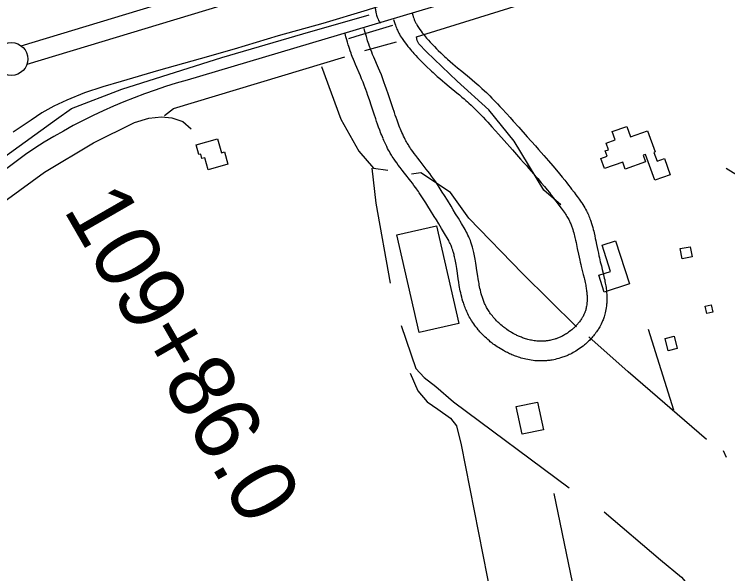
# Model space of a CAD drawing. Extents: x 3146026 to 3183936, y 897894 to 923344.
# Drawn here: x 3163729 to 3164815, y 911183 to 912036 of the extents above; entities that cross this region are included whole.
import ezdxf

# ---------------------------------------------------------------- set-up
doc = ezdxf.new("R2010")
doc.units = 0
for name, color, linetype in [('V-BLDG-OTLN', 7, 'Continuous'), ('V-LEVE-TOET', 7, 'Continuous'), ('V-ROAD-CNTR', 7, 'Continuous'), ('V-SURV-IDEN', 7, 'Continuous'), ('V-SURV-LINE', 7, 'Continuous'), ('V-TOPO-SHOR', 7, 'Continuous')]:
    doc.layers.add(name, color=color, linetype=linetype)

msp = doc.modelspace()

# ---------------------------------------------------------------- linework, layer by layer
at = {"layer": 'V-BLDG-OTLN'}
for points in [[(3164727.9, 911791.2), (3164704.4, 911782.8), (3164690.3, 911822.1), (3164686.8, 911820.8), (3164690.3, 911810.9), (3164659.4, 911799.8), (3164655.6, 911810.5), (3164627.9, 911800.5), (3164622.4, 911815.9), (3164631.8, 911819.3), (3164628.9, 911827.4), (3164634, 911829.3), (3164630.3, 911839.4), (3164644.1, 911844.4), (3164639.6, 911856.8), (3164661.8, 911864.8), (3164667.6, 911848.7), (3164693.4, 911857.9), (3164704.9, 911825.8), (3164703.1, 911825.1), (3164707.9, 911811.7), (3164719.1, 911815.7)], [(3164054.6, 911807.3), (3164024.3, 911798.7), (3164019.1, 911817), (3164014.8, 911815.8), (3164013, 911822.4), (3164010.3, 911821.7), (3164006.1, 911836.6), (3164038.5, 911845.8), (3164044.5, 911824.7), (3164049.3, 911826.1)], [(3164311.8, 911699.6), (3164371.9, 911713.3), (3164406, 911564.6), (3164345.9, 911550.8)], [(3164665.9, 911624.9), (3164627.4, 911612.4), (3164619.1, 911638), (3164637, 911643.8), (3164624.1, 911683.7), (3164644.6, 911690.4)], [(3164761.4, 911666), (3164746.2, 911663.2), (3164743.3, 911678.7), (3164758.5, 911681.5)], [(3164792.9, 911581.9), (3164783.8, 911579.9), (3164781.3, 911590.9), (3164790.4, 911593)], [(3164733.7, 911545.1), (3164738.4, 911526.5), (3164725, 911523.1), (3164720.3, 911541.7)], [(3164493.4, 911438), (3164526.1, 911444.8), (3164535, 911402.6), (3164502.3, 911395.7)]]:
    msp.add_lwpolyline(points, close=True, dxfattribs=at)
at = {"layer": 'V-LEVE-TOET'}
msp.add_lwpolyline([(3164860.5, 912225.7), (3164786.2, 912200.7), (3164711.4, 912177.3), (3164636.1, 912155.4), (3164583.4, 912141), (3164444.8, 912098.4), (3164414.2, 912089), (3164373.8, 912077.4), (3164333.9, 912064.4), (3164309.7, 912055.7), (3164266.4, 912041.7), (3164199, 912021.6), (3164131.2, 912002.8), (3164063.8, 911982.2), (3164012.4, 911967.6), (3163949, 911950.1), (3163891.7, 911932.9), (3163863.8, 911925.1), (3163836.3, 911915.7), (3163809.4, 911904.9), (3163789.6, 911895.6), (3163771.3, 911885.2), (3163754.8, 911874.1), (3163727.7, 911855.9)], dxfattribs=at)
at = {"layer": 'V-ROAD-CNTR'}
for p, q in [((3164250, 912002.2), (3164305.4, 912018.9)), ((3164238.6, 911998.7), (3164250, 912002.2))]:
    msp.add_line(p, q, dxfattribs=at)
for points in [[(3165388.2, 912351.5), (3163992.3, 911935.1)], [(3164278.7, 912047.4), (3164278.7, 912046), (3164278.9, 912044.2), (3164279, 912042.7), (3164279.2, 912041.2), (3164279.5, 912039.8), (3164279.7, 912038.5), (3164280.3, 912036.3), (3164280.8, 912034.4), (3164281.4, 912032.7), (3164281.9, 912031.2), (3164282.4, 912029.9), (3164283.3, 912027.9), (3164284, 912026.3), (3164285.1, 912024.1), (3164286.2, 912022.2)], [(3164334.8, 912037), (3164335.8, 912034.1), (3164336.7, 912031.6), (3164337.5, 912029.6), (3164338.1, 912027.8), (3164338.8, 912026.3), (3164339.3, 912025.1), (3164339.8, 912024), (3164340.7, 912022.1), (3164341.4, 912020.8), (3164341.9, 912019.8), (3164342.8, 912018.4), (3164343.7, 912016.9), (3164344.6, 912015.4), (3164345.6, 912014), (3164346.5, 912012.6), (3164348.5, 912009.9), (3164350.3, 912007.5), (3164352.1, 912005.2), (3164353.8, 912003.1), (3164355.4, 912001.1), (3164356.9, 911999.3), (3164358.4, 911997.6), (3164359.8, 911996.1), (3164362.5, 911993.1), (3164364.9, 911990.5), (3164367, 911988.3), (3164368.9, 911986.4), (3164372.3, 911983), (3164374.8, 911980.5), (3164378.8, 911976.7), (3164382.8, 911972.9), (3164384.9, 911970.9), (3164387, 911969), (3164389, 911967.1), (3164393.1, 911963.5), (3164396.9, 911960.2), (3164400.5, 911957.1), (3164404, 911954.2), (3164410.5, 911948.8), (3164422.1, 911939.2), (3164426.5, 911935.5), (3164430.3, 911932.2), (3164433.6, 911929.4), (3164436.5, 911926.8), (3164439.1, 911924.6), (3164441.3, 911922.6), (3164445.2, 911919), (3164448.1, 911916.3), (3164450.2, 911914.2), (3164453.4, 911911.1), (3164456.5, 911907.9), (3164460.9, 911903.4), (3164464.9, 911899.2), (3164468.6, 911895.2), (3164472.1, 911891.5), (3164478.5, 911884.5), (3164484.2, 911878.3), (3164489, 911872.9), (3164497.5, 911863.4), (3164510.1, 911849.1), (3164522.7, 911834.9), (3164527.2, 911829.8), (3164531.4, 911825), (3164535.4, 911820.5), (3164542.7, 911812.1), (3164549.1, 911804.6), (3164554.6, 911798.1), (3164559.4, 911792.3), (3164563.6, 911787.2), (3164567.3, 911782.6), (3164570.5, 911778.6), (3164573.2, 911775.1), (3164575.7, 911772), (3164577.8, 911769.2), (3164581.5, 911764.4), (3164584.2, 911760.7), (3164586.3, 911757.9), (3164589.4, 911753.7), (3164592.4, 911749.3), (3164593.3, 911748.1), (3164594.9, 911745.6), (3164596.4, 911743.2), (3164597.8, 911740.8), (3164599.1, 911738.5), (3164600.3, 911736.2), (3164601.3, 911734.1)], [(3164306.4, 912027.4), (3164307.5, 912024.3), (3164308.5, 912021.4), (3164309.4, 912018.9), (3164310.3, 912016.7), (3164311.1, 912014.7), (3164311.9, 912012.9), (3164312.6, 912011.4), (3164313.8, 912008.7), (3164314.9, 912006.7), (3164315.7, 912005.1), (3164317, 912002.9), (3164318.4, 912000.7), (3164319.6, 911998.8), (3164320.8, 911997.1), (3164322, 911995.4), (3164324.2, 911992.2), (3164326.4, 911989.3), (3164328.5, 911986.6), (3164330.5, 911984.2), (3164332.4, 911981.9), (3164334.1, 911979.8), (3164335.8, 911977.8), (3164337.4, 911976), (3164340.4, 911972.7), (3164343.1, 911969.9), (3164345.5, 911967.4), (3164347.5, 911965.3), (3164351.2, 911961.7), (3164353.9, 911959), (3164358, 911955), (3164362.2, 911951.1), (3164364.5, 911948.9), (3164366.8, 911946.8), (3164369, 911944.8), (3164373.3, 911941), (3164377.3, 911937.5), (3164381.1, 911934.2), (3164384.7, 911931.2), (3164391.3, 911925.7), (3164402.9, 911916.1), (3164407.1, 911912.6), (3164410.8, 911909.4), (3164414, 911906.7), (3164416.7, 911904.3), (3164419.1, 911902.2), (3164421.2, 911900.3), (3164424.8, 911897), (3164427.4, 911894.6), (3164429.3, 911892.7), (3164432.2, 911889.9), (3164435, 911887), (3164439.2, 911882.7), (3164443.1, 911878.6), (3164446.7, 911874.7), (3164450.1, 911871.1), (3164456.4, 911864.2), (3164461.9, 911858.2), (3164466.7, 911852.9), (3164475.1, 911843.5), (3164487.6, 911829.3), (3164500.2, 911815), (3164504.7, 911809.9), (3164508.9, 911805.2), (3164512.8, 911800.8), (3164520, 911792.5), (3164526.2, 911785.2), (3164531.6, 911778.8), (3164536.3, 911773.2), (3164540.4, 911768.2), (3164543.9, 911763.9), (3164546.9, 911760), (3164549.6, 911756.6), (3164551.9, 911753.6), (3164554, 911751), (3164557.5, 911746.4), (3164560.1, 911742.8), (3164562.1, 911740.2), (3164565, 911736.2), (3164567.9, 911732.1), (3164568.5, 911731.2), (3164569.7, 911729.4), (3164570.7, 911727.7), (3164571.7, 911726), (3164572.7, 911724.3), (3164573.5, 911722.7), (3164574.4, 911720.9)], [(3164290.8, 911846.1), (3164289.7, 911848.8), (3164288.6, 911851.5), (3164287.5, 911854.1), (3164285.6, 911859.1), (3164283.8, 911863.8), (3164282.2, 911868.2), (3164280.8, 911872.3), (3164279.5, 911876.2), (3164277, 911883.4), (3164272.9, 911895.8), (3164269.9, 911905.1), (3164267.6, 911912), (3164265.8, 911917), (3164264.4, 911920.8), (3164263.4, 911923.6), (3164261.8, 911927.8), (3164260.2, 911931.9), (3164258, 911937.3), (3164256.1, 911942), (3164248.9, 911958.8), (3164247.1, 911963.1), (3164245.8, 911966.4), (3164243.8, 911971.3), (3164242.8, 911973.8), (3164241.9, 911976.4), (3164240.6, 911980.1), (3164239.4, 911983.4), (3164238.5, 911986.3), (3164237.7, 911988.8), (3164236.4, 911993.1), (3164235.5, 911996.4), (3164234.2, 912001.3), (3164232.9, 912006.1)], [(3164318.4, 911857.8), (3164317.4, 911860.3), (3164316.4, 911862.8), (3164315.4, 911865.1), (3164313.6, 911869.7), (3164312, 911874.1), (3164310.5, 911878.2), (3164309.1, 911882.1), (3164307.9, 911885.8), (3164305.5, 911892.8), (3164301.4, 911905.2), (3164298.3, 911914.6), (3164295.9, 911921.7), (3164294.1, 911927), (3164292.6, 911931), (3164291.5, 911934.1), (3164289.8, 911938.6), (3164288.1, 911943.1), (3164285.8, 911948.8), (3164283.7, 911953.7), (3164276.5, 911970.4), (3164274.8, 911974.5), (3164273.6, 911977.6), (3164271.8, 911982.2), (3164270.9, 911984.4), (3164270.1, 911986.7), (3164268.9, 911990), (3164267.9, 911992.8), (3164267.1, 911995.3), (3164266.4, 911997.5), (3164265.3, 912001.5), (3164264.4, 912004.5), (3164263.2, 912009.1), (3164261.9, 912013.7)], [(3164451.3, 911584.2), (3164450.2, 911585.9), (3164449.3, 911587.5), (3164448.4, 911589.1), (3164447.6, 911590.6), (3164446.8, 911592.2), (3164446.1, 911593.7), (3164445.4, 911595.2), (3164444.8, 911596.7), (3164444.1, 911598.2), (3164443.6, 911599.7), (3164443, 911601.2), (3164442.5, 911602.6), (3164442, 911604), (3164441.5, 911605.4), (3164441.1, 911606.8), (3164440.3, 911609.6), (3164439.5, 911612.4), (3164438.9, 911615.1), (3164438.3, 911617.7), (3164437.7, 911620.2), (3164437.2, 911622.8), (3164436.8, 911625.2), (3164436.3, 911627.6), (3164435.6, 911632.3), (3164434.9, 911636.8), (3164433.6, 911645.3), (3164432.5, 911652.8), (3164432, 911656.2), (3164431.5, 911659.4), (3164431, 911662.4), (3164430.5, 911665.2), (3164429.9, 911667.8), (3164429.4, 911670.3), (3164428.9, 911672.6), (3164428.4, 911674.8), (3164427.9, 911676.9), (3164427.4, 911678.8), (3164426.9, 911680.6), (3164426.4, 911682.4), (3164425.4, 911685.5), (3164424.5, 911688.3), (3164423.6, 911690.8), (3164422.8, 911692.9), (3164422, 911694.8), (3164421.3, 911696.5), (3164420, 911699.3), (3164419, 911701.4), (3164418.2, 911703), (3164416.9, 911705.4), (3164415.6, 911707.7), (3164410.2, 911716.8), (3164405.4, 911724.8), (3164401.2, 911731.7), (3164397.6, 911737.8), (3164394.3, 911743.1), (3164388.6, 911752.4), (3164384.2, 911759.4), (3164380.9, 911764.6), (3164375.9, 911772.4), (3164370.9, 911780.1), (3164369.3, 911782.5), (3164367.7, 911784.7), (3164366.2, 911786.9), (3164364.7, 911788.9), (3164361.9, 911792.8), (3164359.1, 911796.5), (3164356.5, 911799.8), (3164347, 911811.9), (3164343.5, 911816.4), (3164340.6, 911820.2), (3164338, 911823.6), (3164335.9, 911826.5), (3164334.1, 911829.1), (3164332.6, 911831.3), (3164331.3, 911833.3), (3164330.1, 911835.1), (3164329.2, 911836.5), (3164327.6, 911839.2), (3164326.4, 911841.3), (3164325.6, 911842.7), (3164324.4, 911845), (3164323.2, 911847.4), (3164321.9, 911850.1), (3164320.7, 911852.7), (3164319.5, 911855.3), (3164318.4, 911857.9)], [(3164425.7, 911568.5), (3164424.4, 911570.6), (3164423.2, 911572.7), (3164422, 911574.8), (3164420.9, 911576.9), (3164419.9, 911579), (3164418.9, 911581.1), (3164418, 911583.1), (3164417.1, 911585), (3164416.3, 911587), (3164415.6, 911588.9), (3164414.9, 911590.8), (3164414.2, 911592.7), (3164413.6, 911594.5), (3164413, 911596.3), (3164412.4, 911598.1), (3164411.4, 911601.5), (3164410.5, 911604.8), (3164409.7, 911608.1), (3164409, 911611.2), (3164408.3, 911614.2), (3164407.8, 911617), (3164407.2, 911619.8), (3164406.8, 911622.5), (3164405.9, 911627.6), (3164405.2, 911632.3), (3164403.9, 911641), (3164402.9, 911648.4), (3164402.4, 911651.5), (3164401.9, 911654.4), (3164401.4, 911657.1), (3164401, 911659.6), (3164400.5, 911661.9), (3164400.1, 911664), (3164399.7, 911666), (3164399.2, 911667.8), (3164398.8, 911669.5), (3164398.4, 911671), (3164398, 911672.5), (3164397.6, 911673.8), (3164396.8, 911676.3), (3164396.1, 911678.5), (3164395.5, 911680.3), (3164394.9, 911681.9), (3164394.3, 911683.3), (3164393.8, 911684.4), (3164392.9, 911686.5), (3164392.1, 911688.1), (3164391.6, 911689.1), (3164390.7, 911690.8), (3164389.7, 911692.6), (3164384.4, 911701.5), (3164379.7, 911709.4), (3164375.6, 911716.2), (3164371.9, 911722.2), (3164368.7, 911727.4), (3164363.1, 911736.6), (3164358.8, 911743.4), (3164355.6, 911748.5), (3164350.7, 911756.1), (3164345.8, 911763.6), (3164344.5, 911765.6), (3164343.1, 911767.6), (3164341.8, 911769.5), (3164340.5, 911771.3), (3164337.8, 911774.9), (3164335.3, 911778.2), (3164332.9, 911781.3), (3164323.4, 911793.4), (3164319.8, 911798), (3164316.6, 911802.1), (3164313.9, 911805.8), (3164311.5, 911809.1), (3164309.4, 911812), (3164307.7, 911814.6), (3164306.1, 911816.9), (3164304.8, 911819), (3164303.7, 911820.8), (3164301.7, 911824), (3164300.3, 911826.5), (3164299.2, 911828.4), (3164297.7, 911831.2), (3164296.3, 911834.1), (3164294.8, 911837.3), (3164293.4, 911840.3), (3164292.1, 911843.2), (3164290.9, 911846)], [(3163746.4, 911822.1), (3163589.8, 911705), (3162975.7, 911197.8)], [(3164601.4, 911733.8), (3164602.4, 911731.9), (3164603.3, 911729.8), (3164604.1, 911727.8), (3164604.9, 911725.8), (3164605.6, 911723.9), (3164606.3, 911722.1), (3164607, 911720.2), (3164608.1, 911716.8), (3164609.1, 911713.6), (3164610, 911710.6), (3164610.7, 911707.7), (3164611.4, 911705.1), (3164612, 911702.6), (3164613.1, 911698.1), (3164613.9, 911694.1), (3164614.7, 911690.6), (3164615.9, 911684.7), (3164617.6, 911675.9), (3164618.5, 911671.7), (3164619.4, 911667.6), (3164620.1, 911664.5), (3164620.8, 911661.4), (3164621.5, 911658.5), (3164623.1, 911652.5), (3164624.5, 911646.7), (3164625.9, 911641.2), (3164626.5, 911638.6), (3164627.1, 911636), (3164627.6, 911633.5), (3164628.2, 911631), (3164628.6, 911628.6), (3164629.1, 911626.2), (3164629.5, 911623.9), (3164629.8, 911621.7), (3164630.2, 911619.5), (3164630.4, 911617.4), (3164630.7, 911615.3), (3164630.9, 911613.2), (3164631.1, 911611.3), (3164631.2, 911609.3), (3164631.3, 911607.4), (3164631.4, 911605.6), (3164631.4, 911603.8), (3164631.4, 911602.1), (3164631.4, 911600.4), (3164631.4, 911598.8), (3164631.3, 911597.2), (3164631.2, 911595.6), (3164631.1, 911594), (3164630.8, 911591.2), (3164630.5, 911588.4), (3164630.1, 911585.8), (3164629.6, 911583.3), (3164629.1, 911581), (3164628.5, 911578.9), (3164628, 911576.8), (3164627.4, 911574.9), (3164626.8, 911573.2), (3164626.2, 911571.5), (3164625.6, 911569.9), (3164625, 911568.5), (3164624.5, 911567.1), (3164623.9, 911565.8), (3164622.7, 911563.5), (3164621.7, 911561.4), (3164620.7, 911559.6), (3164619.8, 911558), (3164618.9, 911556.6), (3164618.2, 911555.4), (3164616.8, 911553.3), (3164615.7, 911551.8), (3164614.9, 911550.6), (3164613.6, 911548.9), (3164612.2, 911547.2), (3164611, 911545.6), (3164609.7, 911544.2), (3164608.5, 911542.8), (3164607.2, 911541.4), (3164606, 911540.1), (3164604.8, 911538.8), (3164603.5, 911537.6), (3164602.3, 911536.4), (3164601.1, 911535.3), (3164599.9, 911534.2), (3164598.7, 911533.1), (3164597.6, 911532.2)], [(3164574.2, 911721.2), (3164575, 911719.5), (3164575.7, 911717.9), (3164576.4, 911716.4), (3164577, 911714.8), (3164577.6, 911713.4), (3164578.1, 911711.9), (3164578.6, 911710.5), (3164579.5, 911707.7), (3164580.3, 911705), (3164581.1, 911702.5), (3164581.7, 911700.1), (3164582.3, 911697.8), (3164582.8, 911695.6), (3164583.8, 911691.5), (3164584.6, 911687.8), (3164585.3, 911684.6), (3164586.4, 911678.8), (3164588.2, 911670), (3164589.1, 911665.5), (3164590.1, 911661.1), (3164590.9, 911657.7), (3164591.6, 911654.4), (3164592.4, 911651.2), (3164594, 911645.1), (3164595.4, 911639.4), (3164596.7, 911634.2), (3164597.3, 911631.8), (3164597.8, 911629.4), (3164598.3, 911627.2), (3164598.8, 911625), (3164599.2, 911622.9), (3164599.6, 911620.9), (3164599.9, 911619), (3164600.2, 911617.1), (3164600.5, 911615.4), (3164600.7, 911613.6), (3164600.9, 911612), (3164601, 911610.4), (3164601.2, 911608.9), (3164601.3, 911607.4), (3164601.3, 911606), (3164601.4, 911604.7), (3164601.4, 911603.4), (3164601.4, 911602.1), (3164601.4, 911600.9), (3164601.4, 911599.7), (3164601.4, 911598.6), (3164601.3, 911597.6), (3164601.2, 911596.6), (3164601, 911594.5), (3164600.8, 911592.7), (3164600.5, 911591), (3164600.2, 911589.4), (3164599.9, 911587.9), (3164599.5, 911586.5), (3164599.2, 911585.2), (3164598.8, 911584), (3164598.4, 911582.9), (3164598.1, 911581.9), (3164597.7, 911580.9), (3164597.3, 911580), (3164596.9, 911579.1), (3164596.6, 911578.3), (3164595.9, 911576.8), (3164595.2, 911575.4), (3164594.5, 911574.3), (3164594, 911573.3), (3164593.4, 911572.4), (3164592.9, 911571.6), (3164592, 911570.2), (3164591.3, 911569.2), (3164590.7, 911568.4), (3164589.8, 911567.2), (3164588.9, 911566), (3164588, 911564.9), (3164587.1, 911563.8), (3164586.1, 911562.8), (3164585.2, 911561.8), (3164584.3, 911560.8), (3164583.4, 911559.9), (3164582.5, 911559), (3164581.6, 911558.1), (3164580.7, 911557.3), (3164579.9, 911556.5), (3164579, 911555.8), (3164578.1, 911555)], [(3164578.3, 911555.2), (3164576.4, 911553.6), (3164574.8, 911552.3), (3164573.2, 911551.1), (3164571.6, 911550), (3164570, 911549), (3164568.5, 911548.1), (3164567, 911547.2), (3164565.6, 911546.4), (3164564.2, 911545.6), (3164562.8, 911544.9), (3164561.5, 911544.3), (3164560.2, 911543.7), (3164558.9, 911543.1), (3164557.7, 911542.6), (3164556.5, 911542.2), (3164555.4, 911541.8), (3164554.3, 911541.4), (3164553.2, 911541), (3164552.2, 911540.7), (3164550.1, 911540.1), (3164548.2, 911539.6), (3164546.4, 911539.1), (3164544.8, 911538.8), (3164543.2, 911538.5), (3164541.7, 911538.2), (3164540.4, 911538), (3164539.1, 911537.9), (3164537.9, 911537.7), (3164536.9, 911537.7), (3164534.7, 911537.5), (3164532.9, 911537.4), (3164531.4, 911537.4), (3164530, 911537.4), (3164528.8, 911537.4), (3164527.9, 911537.5), (3164526, 911537.6), (3164524.8, 911537.7), (3164522.8, 911537.9), (3164520.9, 911538.2), (3164518.9, 911538.5), (3164516.9, 911538.9), (3164515, 911539.3), (3164513.1, 911539.8), (3164511.3, 911540.3), (3164509.5, 911540.7), (3164507.8, 911541.3), (3164506.1, 911541.8), (3164504.5, 911542.3), (3164502.9, 911542.9), (3164501.4, 911543.5), (3164499.9, 911544.1), (3164498.5, 911544.6), (3164497.1, 911545.2), (3164495.8, 911545.8), (3164494.5, 911546.4), (3164493.2, 911547), (3164492, 911547.6), (3164490.9, 911548.2), (3164488.6, 911549.4), (3164486.5, 911550.6), (3164484.5, 911551.8), (3164482.7, 911553), (3164481, 911554.1), (3164479.4, 911555.2), (3164477.9, 911556.2), (3164476.5, 911557.3), (3164475.2, 911558.2), (3164474, 911559.2), (3164472.9, 911560.1), (3164471.9, 911560.9), (3164469.9, 911562.6), (3164468.3, 911564.1), (3164466.8, 911565.5), (3164465.6, 911566.7), (3164464.5, 911567.8), (3164463.6, 911568.7), (3164461.9, 911570.5), (3164460.7, 911571.8), (3164459.8, 911572.8), (3164458.4, 911574.4), (3164457.1, 911576), (3164455.8, 911577.7), (3164454.5, 911579.4), (3164453.3, 911581), (3164452.2, 911582.7), (3164451.1, 911584.5)], [(3164597.4, 911532), (3164595.2, 911530.2), (3164592.9, 911528.4), (3164590.6, 911526.7), (3164588.4, 911525.2), (3164586.2, 911523.7), (3164584.1, 911522.4), (3164582, 911521.2), (3164580, 911520.1), (3164578, 911519), (3164576.1, 911518), (3164574.2, 911517.1), (3164572.4, 911516.3), (3164570.7, 911515.5), (3164568.9, 911514.8), (3164567.3, 911514.2), (3164565.7, 911513.6), (3164564.1, 911513), (3164562.6, 911512.5), (3164561, 911512), (3164558.2, 911511.2), (3164555.5, 911510.5), (3164553, 911509.9), (3164550.7, 911509.4), (3164548.4, 911508.9), (3164546.4, 911508.6), (3164544.4, 911508.3), (3164542.6, 911508.1), (3164540.9, 911507.9), (3164539.3, 911507.7), (3164536.4, 911507.5), (3164533.8, 911507.4), (3164531.5, 911507.4), (3164529.6, 911507.4), (3164527.9, 911507.5), (3164526.3, 911507.5), (3164523.8, 911507.7), (3164521.8, 911507.8), (3164519, 911508.2), (3164516.2, 911508.6), (3164513.5, 911509), (3164510.9, 911509.5), (3164508.3, 911510.1), (3164505.9, 911510.7), (3164503.5, 911511.3), (3164501.2, 911511.9), (3164498.9, 911512.6), (3164496.7, 911513.3), (3164494.6, 911514), (3164492.6, 911514.7), (3164490.6, 911515.5), (3164488.7, 911516.2), (3164486.9, 911517), (3164485.1, 911517.8), (3164483.3, 911518.5), (3164481.7, 911519.3), (3164480.1, 911520.1), (3164478.5, 911520.9), (3164476.9, 911521.6), (3164474.1, 911523.2), (3164471.4, 911524.7), (3164468.8, 911526.3), (3164466.5, 911527.7), (3164464.3, 911529.2), (3164462.2, 911530.6), (3164460.3, 911531.9), (3164458.6, 911533.2), (3164456.9, 911534.5), (3164455.4, 911535.7), (3164453.9, 911536.8), (3164452.6, 911538), (3164450.1, 911540.1), (3164448, 911542), (3164446.1, 911543.7), (3164444.5, 911545.3), (3164443.1, 911546.7), (3164441.9, 911548), (3164439.8, 911550.1), (3164438.3, 911551.8), (3164437.1, 911553.2), (3164435.5, 911555.1), (3164433.8, 911557.2), (3164432, 911559.4), (3164430.3, 911561.7), (3164428.7, 911564), (3164427.2, 911566.2), (3164425.9, 911568.2)]]:
    msp.add_lwpolyline(points, dxfattribs=at)
msp.add_arc((3164214.1, 911128.3), 836.7, 105.3748, 123.9902, dxfattribs=at)
at = {"layer": 'V-SURV-LINE'}
for points in [[(3163739.6, 911987.5), (3165502.6, 912521.4)], [(3165511.4, 912492.7), (3163748.3, 911958.8)]]:
    msp.add_lwpolyline(points, dxfattribs=at)
msp.add_circle((3163724.8, 911967.4), 25, dxfattribs=at)
at = {"layer": 'V-TOPO-SHOR'}
for p, q in [((3164262.9, 911980.6), (3164311.4, 911993.8)), ((3164733.6, 911432.6), (3164694.7, 911555.2)), ((3164813.6, 911360.6), (3164809, 911370.4))]:
    msp.add_line(p, q, dxfattribs=at)
for points in [[(3164813.1, 911801.2), (3164960, 911710.7), (3165057.4, 911660), (3165162.3, 911621.1), (3165213.8, 911608.9), (3165230.5, 911606.1), (3165217.9, 911629.3), (3165161.7, 911824.6), (3165130.6, 911924.1), (3165069.8, 912084.6), (3165029.1, 912184.4), (3165021.1, 912200.2), (3165016.3, 912202.8), (3165001.7, 912198.3), (3164932.6, 912177.3)], [(3164561.3, 911745.3), (3164535.4, 911767.6), (3164490.4, 911842.2), (3164451.9, 911890.2), (3164403.7, 911933.6), (3164356.7, 911978.2), (3164345, 911990.5), (3164342.7, 911995.4), (3164341.7, 912001.4), (3164526.2, 912059.2), (3164583.2, 912075.7), (3164903.5, 912170.8), (3164911.9, 912169.4)], [(3162040.6, 910943.7), (3162294.1, 910984.7), (3162552.1, 911035.1), (3162642.8, 911046.3), (3162727, 911071.4), (3162776.2, 911093.1), (3162846.2, 911128), (3162886.9, 911155), (3162925.2, 911183), (3163020.1, 911256.4), (3163191.7, 911394.3), (3163241.4, 911436.5), (3163506.4, 911654.6), (3163712.7, 911817.2), (3163793.6, 911875.6), (3163816.2, 911892.1), (3163892.9, 911921.6), (3164045, 911969.6), (3164168.8, 912005.6), (3164269.3, 912034.5)], [(3163958.1, 911881.5), (3163971.7, 911892), (3164232.5, 911970.6)], [(3164197.2, 911955.9), (3164226.4, 911875.7), (3164254, 911826.8), (3164276.2, 911800.9), (3164297.8, 911797.9)], [(3163040.8, 911191.8), (3163499.9, 911578.2), (3163680.8, 911726.3), (3163775.3, 911794.8), (3163849.9, 911839.8), (3163912.1, 911870.7), (3163934, 911877.3), (3163953.3, 911879.2), (3163968.9, 911877.6), (3163985.6, 911872.4), (3163998.5, 911861.2)], [(3164273.8, 911801), (3164279.7, 911747.9), (3164301.7, 911625.7)], [(3164585.3, 911559.2), (3164503.2, 911640.9), (3164421.1, 911724.9), (3164393.2, 911764.1), (3164348.3, 911794.2), (3164333.8, 911792.2)], [(3164318.1, 911561.5), (3164340.4, 911495.9), (3164353.3, 911482.3), (3164371, 911468.6), (3164398.1, 911445), (3164574, 911314)], [(3164783, 911387.9), (3164664.1, 911491), (3164604.1, 911544.3)], [(3164332, 911489.1), (3164343.7, 911461.9), (3164357.7, 911445), (3164374, 911434.2), (3164393.2, 911420.2), (3164402.3, 911408.6), (3164409.8, 911379.5), (3164501.9, 910910.6), (3164585.7, 910478.1), (3164587.3, 910463.6), (3164701.8, 910489.5), (3164717.5, 910496.3)], [(3164550.5, 911305.4), (3164761.6, 910284.2), (3164890.4, 909600.2), (3165034.8, 908874.5), (3165047.7, 908814.1), (3165042.2, 908764.6), (3164970.4, 908470.7), (3164847.8, 907979.5), (3164825.9, 907934.6), (3164802.4, 907904.2)], [(3164627.2, 911277.7), (3164713.2, 911204.4), (3164745, 911178.3), (3164780, 911136.4), (3164830, 911071.3), (3164884.3, 910984.4), (3164898.2, 910962.3), (3164906.5, 910956.1), (3164924.2, 910944.8)]]:
    msp.add_lwpolyline(points, dxfattribs=at)

# ---------------------------------------------------------------- texts
at = {"layer": 'V-SURV-IDEN'}
msp.add_text('109+86.0', height=100, rotation=299.9413, dxfattribs=at).set_placement((3163803, 911738.4))

doc.saveas('drawing.dxf')
